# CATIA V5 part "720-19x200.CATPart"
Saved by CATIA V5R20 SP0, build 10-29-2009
Part number: 720-19x200
Definition: NONE
Nomenclature: 720-19x200
Source: Unknown
Description: 720-19x200
Bounding box of the stored display mesh (mm): x 0 to 200, y -9.5 to 9.5, z -9.5 to 9.5
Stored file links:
  C:\Users\Utente\Desktop\IO LAVORO\3D X SITO CF\X SITO\720\720-19x200.CATPart
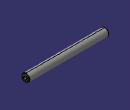
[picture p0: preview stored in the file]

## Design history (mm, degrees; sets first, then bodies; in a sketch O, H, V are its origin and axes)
Body1 "720-19x200" (main body)
  Solid1: solid without history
